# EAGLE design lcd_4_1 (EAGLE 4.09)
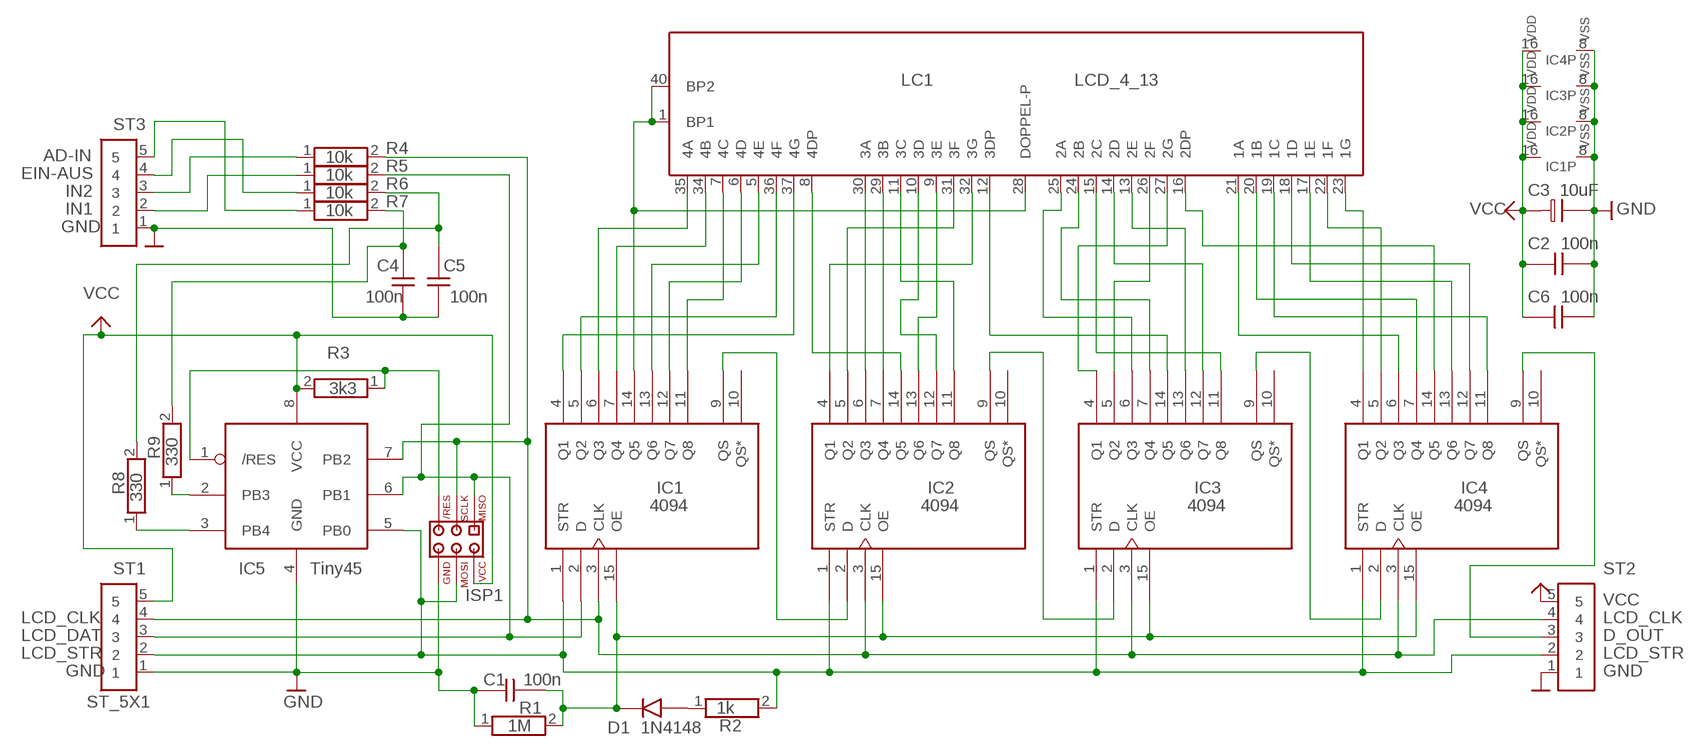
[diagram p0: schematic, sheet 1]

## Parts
C1  100n  CAP01805  [0805]
C2  100n  CAP01805  [0805]
C3  10uF  ELKO-SMD6.3X5.4  [SMD-6,3X5]
C4  100n  CAP01805  [0805]
C5  100n  CAP01805  [0805]
C6  100n  CAP01805  [0805]
D1  1N4148  DIO030805  [DIO0805]
IC1  4094  [SO-16]
IC2  4094  [SO-16]
IC3  4094  [SO-16]
IC4  4094  [SO-16]
IC5  Tiny45  ATTINY13SOL8  [MINO_SO8-2]
ISP1  AVR_ISPNORMAL  [CON03X2]
LC1  LCD_4_13  [DIL40LCD]
R1  1M  RES04-805  [0805]
R2  1k  RES04-805  [0805]
R3  3k3  RES04-805  [0805]
R4  10k  RES04-805  [0805]
R5  10k  RES04-805  [0805]
R6  10k  RES04-805  [0805]
R7  10k  RES04-805  [0805]
R8  330  RES04-805  [0805]
R9  330  RES04-805  [0805]
ST1  ST_5X1  [5X1]
ST2  ST_5X1  [5X1]
ST3  ST_5X1  [5X1]

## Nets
AD-IN: R7.1 ST3.5
D_OUT: IC4.9(QS) ST2.3
EIN-AUS: R6.1 ST3.4
GND: C1.1 C2.2 C3.N C4.1 C5.1 C6.1 IC1.8(VSS) IC2.8(VSS) IC3.8(VSS) IC4.8(VSS) IC5.4(GND) ISP1.6 R1.1 ST1.1 ST2.1 ST3.1
IN1: R5.1 ST3.2
IN2: R4.1 ST3.3
LCD_CLK: IC1.3(CLK) IC2.3(CLK) IC3.3(CLK) IC4.3(CLK) IC5.7(PB2) ISP1.3 R4.2 ST1.4 ST2.4
LCD_DAT: IC1.2(D) IC5.6(PB1) ISP1.1 R5.2 ST1.3
LCD_STR: IC1.1(STR) IC2.1(STR) IC3.1(STR) IC4.1(STR) IC5.5(PB0) ISP1.4 R2.2 ST1.2 ST2.2
N$1: IC1.4(Q1) LC1.37(4G)
N$2: IC2.4(Q1) LC1.32(3G)
N$3: IC3.4(Q1) LC1.27(2G)
N$4: IC4.4(Q1) LC1.23(1G)
N$5: IC4.5(Q2) LC1.22(1F)
N$6: IC3.5(Q2) LC1.26(2F)
N$7: IC2.5(Q2) LC1.31(3F)
N$8: IC1.5(Q2) LC1.36(4F)
N$9: IC1.6(Q3) LC1.35(4A)
N$10: IC1.7(Q4) LC1.34(4B)
N$11: IC2.6(Q3) LC1.30(3A)
N$12: IC2.7(Q4) LC1.29(3B)
N$13: IC3.6(Q3) LC1.25(2A)
N$14: IC3.7(Q4) LC1.24(2B)
N$15: IC4.6(Q3) LC1.21(1A)
N$16: IC4.7(Q4) LC1.20(1B)
N$17: IC1.14(Q5) LC1.1(BP1) LC1.28(DOPPEL-P) LC1.40(BP2)
N$18: IC1.13(Q6) LC1.5(4E)
N$19: IC1.12(Q7) LC1.6(4D)
N$20: IC2.14(Q5) LC1.8(4DP)
N$21: IC1.11(Q8) LC1.7(4C)
N$22: IC2.13(Q6) LC1.9(3E)
N$23: IC2.12(Q7) LC1.10(3D)
N$24: IC2.11(Q8) LC1.11(3C)
N$25: IC4.13(Q6) LC1.17(1E)
N$26: IC3.13(Q6) LC1.13(2E)
N$27: IC3.12(Q7) LC1.14(2D)
N$28: IC3.14(Q5) LC1.12(3DP)
N$29: IC4.12(Q7) LC1.18(1D)
N$30: IC4.11(Q8) LC1.19(1C)
N$32: IC4.14(Q5) LC1.16(2DP)
N$33: IC1.9(QS) IC2.2(D)
N$34: IC2.9(QS) IC3.2(D)
N$35: IC3.9(QS) IC4.2(D)
N$36: IC3.11(Q8) LC1.15(2C)
N$39: IC5.1(/RES) ISP1.5 R3.1
N$42: D1.1(A) R2.1
N$43: IC5.3(PB4) R8.1
N$44: IC5.2(PB3) R9.1
N$49: C4.2 R7.2 R9.2
N$50: C5.2 R6.2 R8.2
OE: C1.2 D1.2(K) IC1.15(OE) IC2.15(OE) IC3.15(OE) IC4.15(OE) R1.2
VCC: C2.1 C3.P C6.2 IC1.16(VDD) IC2.16(VDD) IC3.16(VDD) IC4.16(VDD) IC5.8(VCC) ISP1.2 R3.2 ST1.5 ST2.5
Unconnected: IC1.10(QS*) IC2.10(QS*) IC3.10(QS*) IC4.10(QS*)

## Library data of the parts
C1 C2 C4-C6 = DISCRETE:CAP01
C3 = DISCRETE:ELKO-SMD
D1 = DISCRETE:DIO03
IC1-IC4 = SMD_40XX:4094
IC5 = MINO:ATTINY13
ISP1 = CONNEC:AVR_ISP
LC1 = MINO:LCD_4_13
R1-R9 = DISCRETE:RES04
ST1-ST3 = CONNEC:ST_5X1

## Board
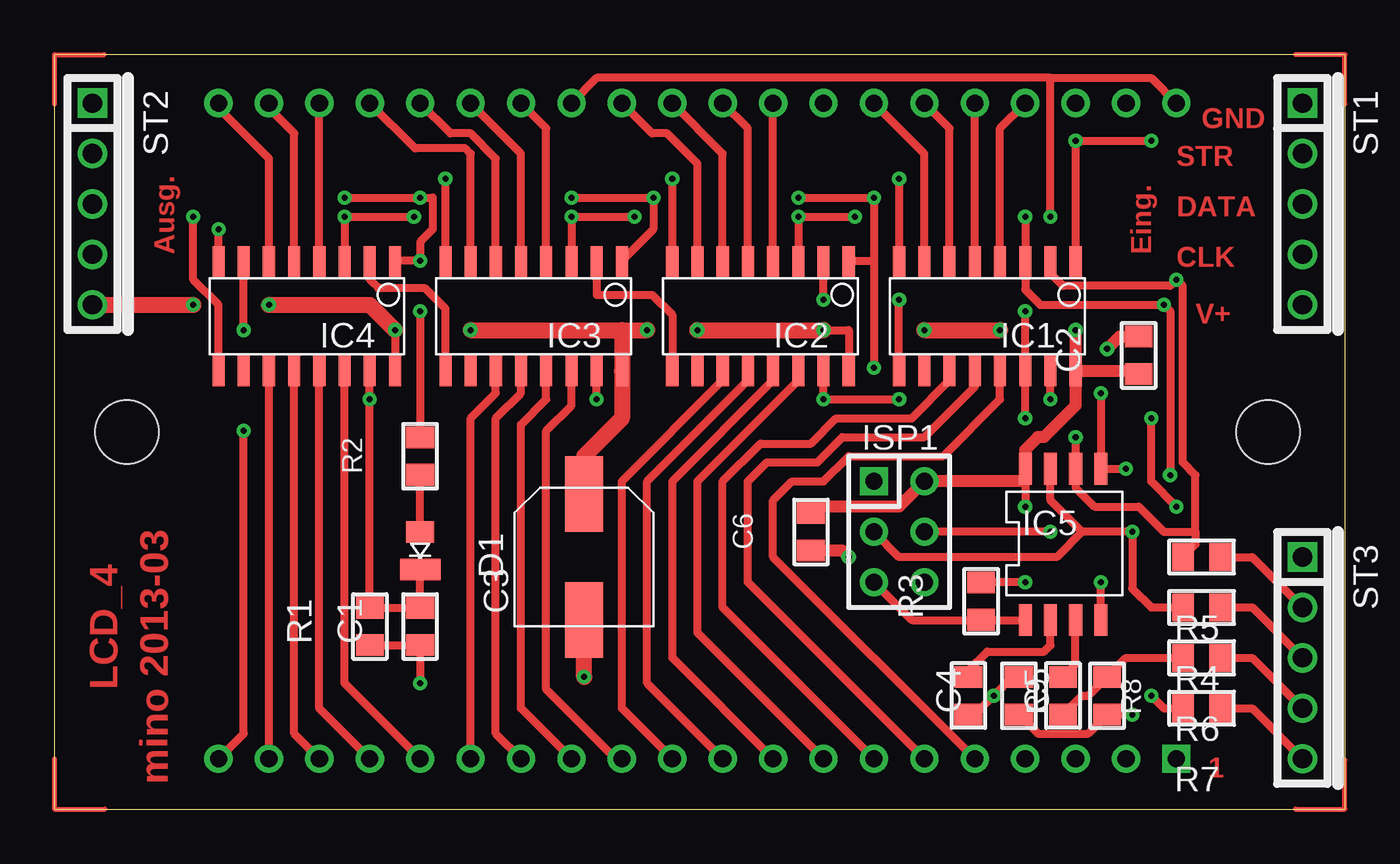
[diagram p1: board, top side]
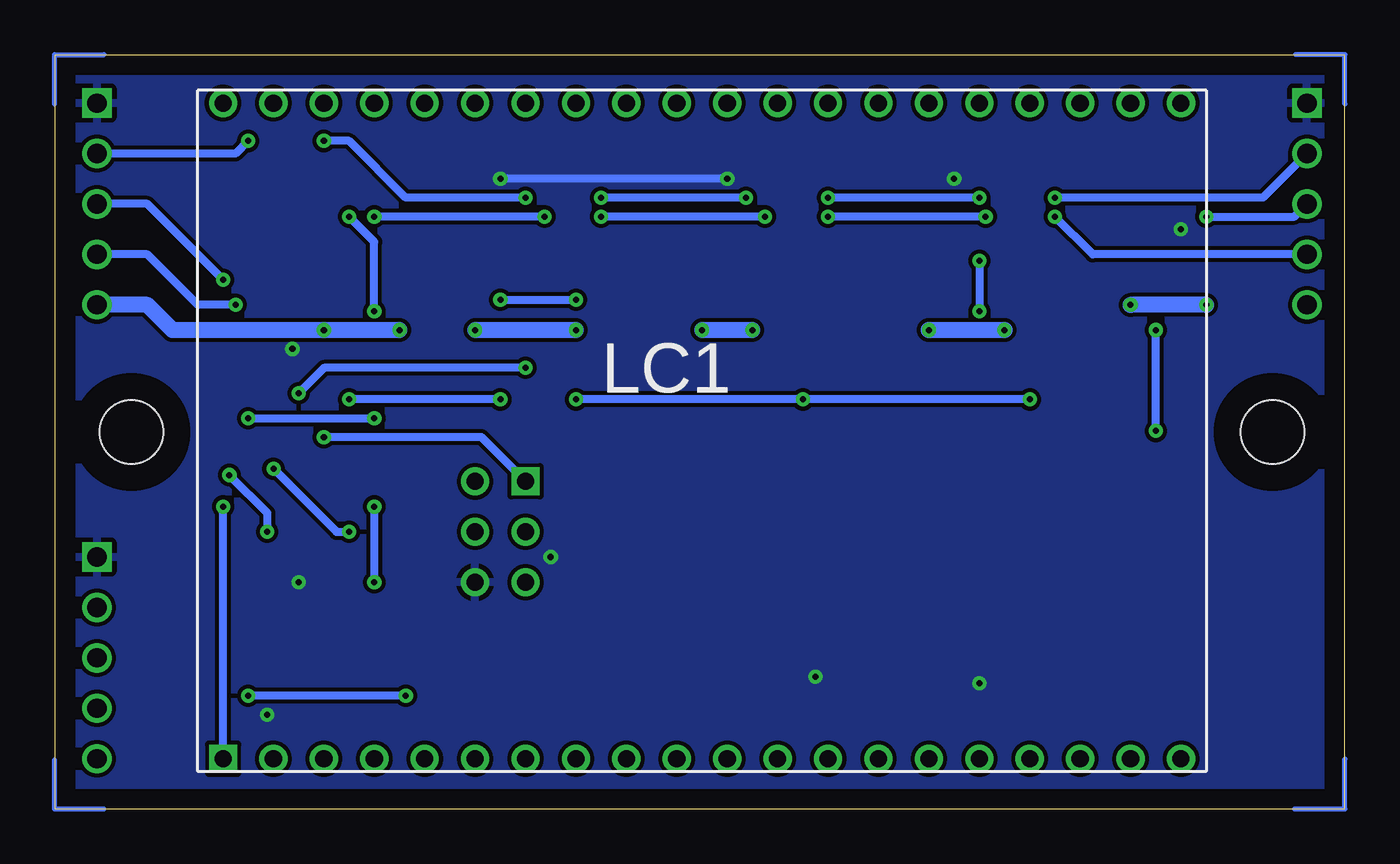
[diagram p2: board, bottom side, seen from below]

Size 65 x 38 mm. Coordinates in mm from the lower left corner, seen from the top.
Outline: 0,0 65,0 65,38 0,38 0,0
Copper layers used: Top, Bottom
Holes 3.2 mm at 61.13,19 3.63,19
bRestrict: area 58.4,16.2 to 63.9,21.8; area 0.9,16.2 to 6.4,21.8

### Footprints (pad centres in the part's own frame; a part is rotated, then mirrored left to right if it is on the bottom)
0805 = smd 1.092 x 1.397: 1 -0.94,0; 2 0.94,0
SMD-6,3X5 = smd 3.81 x 1.93: N -3.175,0; P 3.175,0
DIO0805 = smd 1.092 x 1.397: 1 -0.94,0 | smd 1.092 x 2.032: 2 0.94,0
SO-16 = smd 0.61 x 1.524: 1 -3.81,-2.819; 2 -2.54,-2.819; 3 -1.27,-2.819; 4 0,-2.819; 5 1.27,-2.819; 6 2.54,-2.819; 7 3.81,-2.819; 8 5.08,-2.819; 9 5.08,2.692; 10 3.81,2.692; 11 2.54,2.692; 12 1.27,2.692; 13 0,2.692; 14 -1.27,2.692; 15 -2.54,2.692; 16 -3.81,2.692
MINO_SO8-2 = smd 0.66 x 1.6: 1 0,-0.635; 2 1.27,-0.635; 3 2.54,-0.635; 4 3.81,-0.635; 5 3.81,6.985; 6 2.54,6.985; 7 1.27,6.985; 8 0,6.985
CON03X2 = drill 0.864 pad 1.422 square: 1 0,0 | drill 0.864 pad 1.422 round: 2 0,2.54; 3 2.54,0; 4 2.54,2.54; 5 5.08,0; 6 5.08,2.54
DIL40LCD = drill 0.864 pad 1.422 square: 1 0,0 | drill 0.864 pad 1.422 round: 2 2.54,0; 3 5.08,0; 4 7.62,0; 5 10.16,0; 6 12.7,0; 7 15.24,0; 8 17.78,0; 9 20.32,0; 10 22.86,0; 11 25.4,0; 12 27.94,0; 13 30.48,0; 14 33.02,0; 15 35.56,0; 16 38.1,0; 17 40.64,0; 18 43.18,0; 19 45.72,0; 20 48.26,0; 21 48.26,33.02; 22 45.72,33.02; 23 43.18,33.02; 24 40.64,33.02; 25 38.1,33.02; 26 35.56,33.02; 27 33.02,33.02; 28 30.48,33.02; 29 27.94,33.02; 30 25.4,33.02; 31 22.86,33.02; 32 20.32,33.02; 33 17.78,33.02; 34 15.24,33.02; 35 12.7,33.02; 36 10.16,33.02; 37 7.62,33.02; 38 5.08,33.02; 39 2.54,33.02; 40 0,33.02
5X1 = drill 0.965 pad 1.422 square: 1 0,0 | drill 0.965 pad 1.422 round: 2 2.54,0; 3 5.08,0; 4 7.62,0; 5 10.16,0

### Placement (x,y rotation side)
C1  18.42,9.21 90 top
C2  54.61,22.86 90 top
C3  26.67,12.7 90 top
C4  48.58,5.71 90 top
C5  53.02,5.71 90 top
C6  38.1,13.97 90 top
D1  18.42,13.02 270 top
IC1  47.62,24.77 180 top
IC2  36.2,24.77 180 top
IC3  24.77,24.77 180 top
IC4  13.33,24.77 180 top
IC5  48.89,10.16 0 top
ISP1  41.27,16.51 270 top
LC1  56.52,2.54 0 bottom
R1  15.88,9.21 90 top
R2  18.42,17.78 90 top
R3  46.67,10.48 90 top
R4  57.78,10.16 180 top
R5  57.78,12.7 180 top
R6  57.78,7.62 180 top
R7  57.78,5.08 180 top
R8  50.8,5.71 270 top
R9  46.04,5.71 270 top
ST1  62.86,35.56 270 top
ST2  1.91,35.56 270 top
ST3  62.86,12.7 270 top

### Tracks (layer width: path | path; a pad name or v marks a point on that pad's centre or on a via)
AD-IN
  Top 0.406: R7.1 60.32,5.08 ST3.5
D_OUT  (via drill 0.3)
  Top 0.406: IC4.9 8.26,25.4 6.98,26.67 v6.98,29.84
  Bottom 0.406: v6.98,29.84 2.54,29.84 ST2.3
EIN-AUS
  Top 0.406: R6.1 60.32,7.62 ST3.4
GND  (via drill 0.3)
  Top 0.406: 42.54,27.43 IC1.8 v42.54,31.75 | IC2.8 v31.12,31.75 | IC3.8 v19.69,31.75 | IC4.8 v8.26,29.21 | IC5.4 v52.7,11.43 | R1.1 18.4,8.27 18.42,8.26 C1.1 v18.42,6.35 | C4.1 49.53,3.82 49.53,3.81 52.07,3.81 53.02,4.76 C5.1 54.28,4.78 v54.29,4.76
  Top 0.61: C2.2 53.64,23.8 v53.02,23.18 | C6.1 39.67,13.03 v40,12.7
  Top 0.813: v26.67,6.67 C3.N
  Bottom 0.406: v31.12,31.75 v42.54,31.75 v31.12,31.75
  pour Bottom: 0.64,37.47 0.64,0.64 64.14,0.64 64.14,37.47
IN1
  Top 0.406: R5.1 60.32,12.7 ST3.2
IN2
  Top 0.406: R4.1 60.32,10.16 ST3.3
LCD_CLK  (via drill 0.3)
  Top 0.406: v48.89,29.84 IC1.3 48.89,26.16 49.66,25.4 v55.88,25.4 56.2,25.08 v56.2,16.83 | IC2.3 v37.46,29.84 v40.32,29.84 | IC3.3 v26.04,29.84 v29.21,29.84 | IC4.3 v14.61,29.84 v18.1,29.84 | IC5.7 50.16,15.56 51.75,13.97 | 51.75,13.97 v54.29,13.97 54.29,11.11 55.24,10.16 R4.2 | ISP1.3 42.54,12.7 50.48,12.7 51.75,13.97
  Bottom 0.406: v55.88,25.4 57.78,25.4 60.32,27.94 ST1.4 | v40.32,29.84 v48.89,29.84 | ST2.4 12.7,27.94 v14.61,29.84 | v18.1,29.84 v26.04,29.84 | v29.21,29.84 v37.46,29.84 | v54.29,13.97 54.29,14.92 v56.2,16.83
LCD_DAT  (via drill 0.3)
  Top 0.406: 57.47,13.97 57.47,13.34 56.83,12.7 R5.2 | 57.47,13.97 57.47,16.83 56.83,17.46 56.83,26.35 v56.52,26.67 56.2,26.35 50.8,26.35 50.16,26.99 IC1.2 50.16,27.62 | v51.43,18.73 IC5.6 51.43,16.19 52.39,15.24 54.61,15.24 55.88,13.97 57.47,13.97
  Bottom 0.406: v56.52,26.67 60.32,30.48 ST1.3 | ISP1.1 43.5,18.73 v51.43,18.73
LCD_STR  (via drill 0.3)
  Top 0.406: IC1.1 v51.43,33.66 v55.24,33.66 | IC2.1 41.24,27.58 41.27,27.62 | IC4.1 17.15,27.62 v18.42,27.62 18.42,28.57 19.05,29.21 19.05,30.8 v18.42,30.8 v14.61,30.8 | 41.27,27.62 v41.27,22.23 | IC3.1 28.58,27.62 30.16,29.21 v30.16,30.8 v26.04,30.8 | 41.27,27.62 v41.27,30.8 v37.46,30.8 | v18.42,25.08 R2.2 | v50.16,13.97 ISP1.4 | v52.7,20.95 IC5.5 v53.98,17.14
  Bottom 0.406: ST1.2 55.88,33.02 v55.24,33.66 | v52.7,20.95 51.43,22.23 v41.27,22.23 | v51.43,33.66 50.16,33.66 47.31,30.8 v41.27,30.8 | v18.42,27.62 v18.42,25.08 | v30.16,30.8 v37.46,30.8 | v18.42,30.8 v26.04,30.8 | v14.61,30.8 4.13,30.8 ST2.2 | v50.16,13.97 50.8,13.97 v53.98,17.14
N$1
  Top 0.406: IC1.4 47.62,34.29 LC1.37
N$2
  Top 0.406: IC2.4 LC1.32
N$3
  Top 0.406: IC3.4 24.77,34.29 LC1.27
N$4
  Top 0.406: IC4.4 LC1.23
N$5
  Top 0.406: IC4.5 12.06,34.04 10.79,35.31 LC1.22
N$6
  Top 0.406: IC3.5 23.5,33.02 LC1.26
N$7
  Top 0.406: IC2.5 34.92,34.29 LC1.31
N$8
  Top 0.406: IC1.5 LC1.36
N$9
  Top 0.406: IC1.6 45.09,34.29 LC1.35
N$10
  Top 0.406: IC1.7 43.81,33.02 LC1.34
N$11
  Top 0.406: IC2.6 33.66,33.02 LC1.30
N$12
  Top 0.406: IC2.7 32.38,32.51 30.86,34.04 30.1,34.04 LC1.29
N$13
  Top 0.406: IC3.6 22.23,32.77 20.96,34.04 19.94,34.04 LC1.25
N$14
  Top 0.406: IC3.7 20.96,33.02 20.7,33.27 18.16,33.27 LC1.24
N$15
  Top 0.406: IC4.6 10.79,32.77 8.26,35.31 LC1.21
N$16  (via drill 0.3)
  Top 0.406: v9.53,24.13 IC4.7 | v9.53,19.05 9.53,3.81 LC1.20
  Bottom 0.406: v9.53,19.05 v9.53,24.13
N$17  (via drill 0.3)
  Top 0.406: LC1.28 27.31,36.83 50.16,36.83 | 50.16,36.83 55.24,36.83 LC1.40 | v48.89,25.08 IC1.14 v48.89,19.68 | v50.16,29.84 50.16,36.83 | v56.52,15.24 55.24,16.51 v55.24,19.68
  Bottom 0.406: v48.89,25.08 48.89,28.57 v50.16,29.84 | v55.24,19.68 v48.89,19.68 | LC1.1 v56.52,15.24
N$18
  Top 0.406: IC1.13 47.62,20.64 44.77,17.78 40,17.78 38.73,16.51 37.15,16.51 36.2,15.56 36.2,12.7 LC1.5
N$19
  Top 0.406: IC1.12 46.35,21.27 43.81,18.73 39.69,18.73 38.42,17.46 35.88,17.46 34.92,16.51 34.92,11.43 LC1.6
N$20
  Top 0.406: IC2.14 37.46,21.59 32.38,16.51 32.38,8.89 LC1.8
N$21
  Top 0.406: IC1.11 45.09,21.59 43.18,19.68 39.37,19.68 38.1,18.41 35.56,18.41 33.66,16.51 33.66,10.16 LC1.7
N$22
  Top 0.406: IC2.13 36.2,21.59 31.12,16.51 31.12,7.62 LC1.9
N$23
  Top 0.406: IC2.12 34.92,21.59 29.85,16.51 29.85,6.35 LC1.10
N$24
  Top 0.406: IC2.11 33.66,21.59 28.58,16.51 28.58,5.08 LC1.11
N$25
  Top 0.406: IC4.13 13.33,5.08 LC1.17
N$26
  Top 0.406: IC3.13 24.77,20.64 23.5,19.37 23.5,5.08 LC1.13
N$27
  Top 0.406: IC3.12 23.5,20.95 22.23,19.68 22.23,3.81 LC1.14
N$28
  Top 0.406: IC3.14 26.04,20.32 24.77,19.05 24.77,6.03 28.26,2.54 LC1.12
N$29
  Top 0.406: IC4.12 12.06,3.81 LC1.18
N$30
  Top 0.406: LC1.19 IC4.11
N$32
  Top 0.406: LC1.16 14.61,6.35 IC4.14
N$33  (via drill 0.3)
  Top 0.406: IC1.9 v42.54,25.65 | v38.73,25.65 IC2.2
  Bottom 0.406: v42.54,25.65 v38.73,25.65
N$34
  Top 0.406: IC2.9 31.12,24.89 30.1,25.91 27.31,25.91 IC3.2
N$35
  Top 0.406: IC3.9 19.69,25.21 18.67,26.23 16.32,26.23 15.88,26.67 IC4.2
N$36
  Top 0.406: IC3.11 22.23,20.95 20.96,19.68 LC1.15
N$39
  Top 0.406: IC5.1 46.67,9.53 R3.1 46.66,9.53 43.18,9.53 ISP1.5
N$42
  Top 0.406: D1.1 R2.1
N$43
  Top 0.406: R8.1 51.43,7.29 IC5.3
N$44
  Top 0.406: IC5.2 50.16,8.26 49.85,7.94 46.99,7.94 46.04,6.99 R9.1
N$49  (via drill 0.3)
  Top 0.406: 46.05,4.76 R9.2 46.34,4.78 46.35,4.76 v47.29,5.7 v47.29,5.71 v47.31,5.71 48.26,6.67 48.58,6.67 C4.2 | v55.24,5.71 55.88,5.08 R7.2
  Bottom 0.406: v47.31,5.71 v55.24,5.71
N$50
  Top 0.406: R8.2 51.74,5.71 52.07,5.71 53.02,6.67 | 53.02,6.67 C5.2 | R6.2 53.98,7.62 53.02,6.67
OE  (via drill 0.3)
  Top 0.406: 15.88,22.35 IC4.15 15.88,21.59 | v50.16,20.64 IC1.15 | v42.54,20.64 v38.73,20.64 IC2.15 | 15.88,21.59 v15.88,20.64 R1.2 | v27.31,20.64 IC3.15 | D1.2 C1.2 15.89,10.15 R1.2 | R1.2 | 15.88,21.59 15.88,21.91
  Bottom 0.406: v15.88,20.64 v27.31,20.64 v38.73,20.64 | v42.54,20.64 v50.16,20.64
S$1
  Bottom 0.254: 2.54,0 0,0 0,2.54
S$2
  Top 0.254: 2.54,0 0,0 0,2.54
S$3
  Bottom 0.254: 0,35.51 0,38 2.49,38
S$4
  Top 0.254: 2.49,38 0,38 0,35.51
S$5
  Top 0.254: 62.51,38 65,38 65,35.51
S$6
  Bottom 0.254: 62.51,38 65,38 65,35.51
S$7
  Bottom 0.254: 65,2.49 65,0 62.51,0
S$8
  Top 0.254: 62.51,0 65,0 65,2.49
VCC  (via drill 0.3)
  Top 0.406: v38.73,24.13 40,24.13 IC2.16 | v17.15,24.13 IC4.16 | C2.1 54.61,21.91 54.45,22.07 | 38.1,14.92 C6.2 | R3.2 v48.89,11.43 | 48.89,16.51 v48.89,15.24
  Top 0.61: v51.43,24.13 IC1.16 | IC1.16 54.45,22.07 | IC1.16 51.43,20.32 49.85,18.73 49.53,18.73 48.89,18.1 IC5.8 48.89,16.51 ISP1.2 42.54,15.24 38.42,15.24 38.1,14.92
  Top 0.813: v20.96,24.13 28.58,24.13 | v43.81,24.13 v47.62,24.13 | 28.58,24.13 v29.85,24.13 | v32.38,24.13 v38.73,24.13 | 28.58,24.13 IC3.16 28.58,19.68 26.67,17.78 C3.P | v17.15,24.13 15.88,25.4 v10.79,25.4 | ST2.5 v6.98,25.4
  Bottom 0.406: v48.89,15.24 v48.89,11.43
  Bottom 0.813: v17.15,24.13 v20.96,24.13 | v38.73,24.13 v43.81,24.13 | v47.62,24.13 v51.43,24.13 59.05,24.13 60.32,25.4 ST1.5 | v29.85,24.13 v32.38,24.13 | v6.98,25.4 v10.79,25.4

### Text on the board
Top: GND | STR | DATA | Ausg. | Eing. | CLK | V+ | LCD_4 | 1 | mino 2013-03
